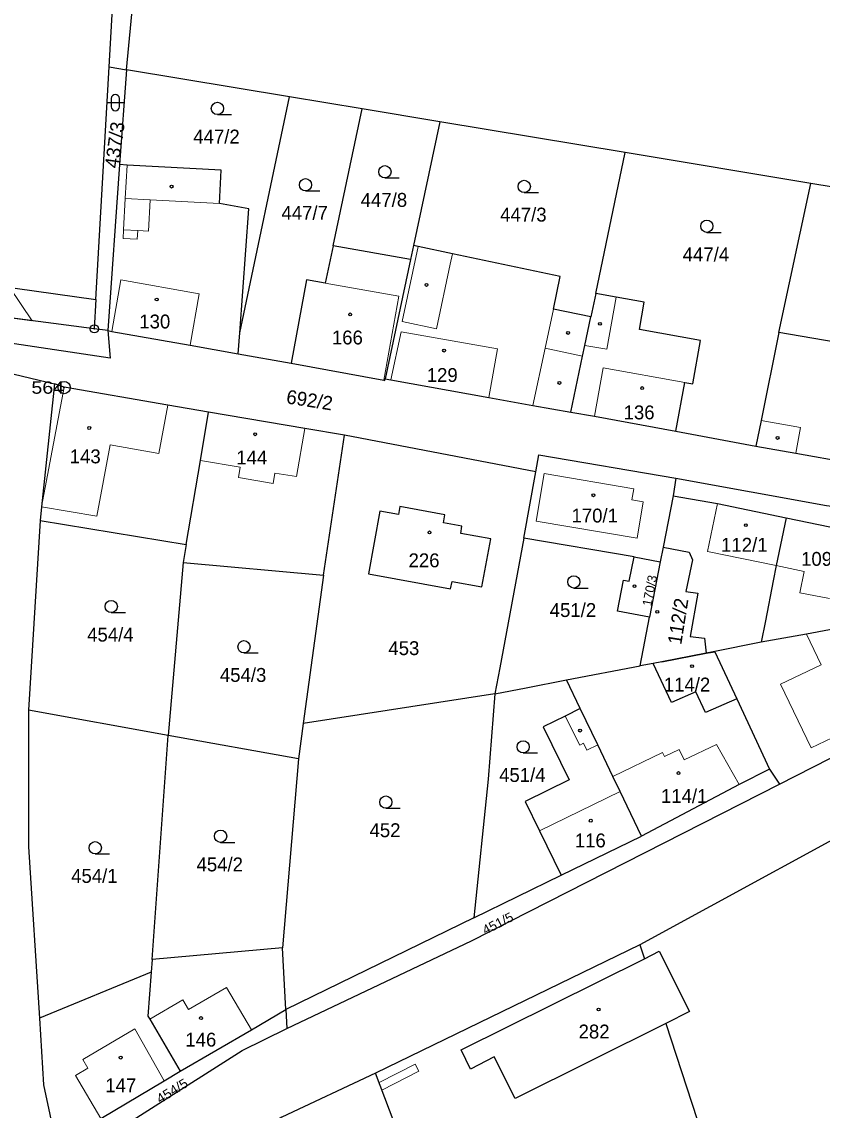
# Model space of a CAD drawing. Extents: x -758887 to -754328, y -1031688 to -1029144.
# Drawn here: x -756696 to -756598, y -1030326.2 to -1030192.8 of the extents above; entities that cross this region are included whole.
import ezdxf
from ezdxf.enums import TextEntityAlignment as Align

# ---------------------------------------------------------------- set-up
doc = ezdxf.new("R2010")
doc.units = 0
doc.header["$LTSCALE"] = 0.68
for name, color, linetype, lineweight in [('1', 7, 'Continuous', 25), ('13', 7, 'Continuous', 13), ('3', 7, 'Continuous', 25), ('4', 7, 'Continuous', 13), ('5', 7, 'Continuous', 25), ('8', 7, 'Continuous', 25)]:
    doc.layers.add(name, color=color, linetype=linetype, lineweight=lineweight)
doc.layers.add('2', color=7, linetype='Continuous')

msp = doc.modelspace()

# ---------------------------------------------------------------- linework, layer by layer
at = {"layer": '1'}
for p, q in [((-756685.29, -1030198.37), (-756683.17, -1030198.72)), ((-756683.17, -1030198.72), (-756684.01, -1030210.35)), ((-756654.32, -1030203.52), (-756663.2, -1030202.04)), ((-756657.85, -1030220.28), (-756654.32, -1030203.52)), ((-756644.8, -1030205.1), (-756654.32, -1030203.52)), ((-756625.69, -1030226.14), (-756622.11, -1030208.87)), ((-756684.01, -1030210.35), (-756685.47, -1030230.69)), ((-756648.38, -1030221.99), (-756657.85, -1030220.28)), ((-756687.12, -1030230.47), (-756737.93, -1030223.79)), ((-756625.69, -1030226.14), (-756626.3, -1030229.01)), ((-756686.91, -1030226.87), (-756687.12, -1030230.47)), ((-756685.47, -1030230.69), (-756687.12, -1030230.47)), ((-756584.9, -1030234.13), (-756603.26, -1030230.9)), ((-756669.48, -1030233.55), (-756663.02, -1030234.67)), ((-756700.62, -1030235.14), (-756691.98, -1030237.21)), ((-756633.02, -1030248.01), (-756656.47, -1030243.49)), ((-756615.89, -1030242.99), (-756606.1, -1030244.83)), ((-756634.51, -1030256.1), (-756633.02, -1030248.01)), ((-756615.89, -1030248.78), (-756616.22, -1030250.92)), ((-756693.76, -1030253.97), (-756695.18, -1030277.2)), ((-756620.97, -1030258.39), (-756634.51, -1030256.1)), ((-756676.24, -1030259.12), (-756678.07, -1030280.29)), ((-756620.97, -1030258.39), (-756617.79, -1030259.04)), ((-756659.04, -1030260.65), (-756661.53, -1030278.84)), ((-756599.88, -1030267.89), (-756605.42, -1030268.88)), ((-756612.17, -1030270.21), (-756617.59, -1030271.27)), ((-756618.67, -1030271.47), (-756620.26, -1030271.77)), ((-756617.59, -1030271.27), (-756618.67, -1030271.47)), ((-756638.04, -1030275.18), (-756661.53, -1030278.84)), ((-756603.2, -1030286.25), (-756581.92, -1030275.41)), ((-756608.43, -1030275.79), (-756612.24, -1030277.5)), ((-756662.12, -1030283.18), (-756678.07, -1030280.29)), ((-756640.63, -1030302.65), (-756663.67, -1030313.89)), ((-756620.28, -1030305.94), (-756652.67, -1030321.7)), ((-756620.28, -1030305.94), (-756619.72, -1030307.65)), ((-756642.2, -1030318.84), (-756619.72, -1030307.65)), ((-756680.15, -1030309.29), (-756693.84, -1030314.92)), ((-756663.67, -1030313.89), (-756663.55, -1030316.2)), ((-756614.22, -1030314.14), (-756617.12, -1030315.59)), ((-756617.12, -1030315.59), (-756635.56, -1030324.79)), ((-756647.29, -1030335.79), (-756652.67, -1030321.7))]:
    msp.add_line(p, q, dxfattribs=at)
for points in [[(-756685.29, -1030198.37), (-756679.09, -1030089.54), (-756699.14, -1030088.53)], [(-756683.17, -1030198.72), (-756678.44, -1030149.27), (-756677.83, -1030132.01)], [(-756696.82, -1030225.47), (-756686.91, -1030226.87), (-756685.29, -1030198.37)], [(-756669.29, -1030230.97), (-756663.2, -1030202.04), (-756683.17, -1030198.72)], [(-756622.11, -1030208.87), (-756644.8, -1030205.1), (-756648.01, -1030220.26)], [(-756603.26, -1030230.9), (-756599.37, -1030212.64), (-756622.11, -1030208.87)], [(-756669.29, -1030230.97), (-756668.18, -1030215.77), (-756671.79, -1030215.12), (-756671.57, -1030211.03), (-756683.1, -1030210.4), (-756684.01, -1030210.35)], [(-756584.9, -1030234.13), (-756582.7, -1030215.41), (-756599.37, -1030212.64)], [(-756657.85, -1030220.28), (-756658.82, -1030224.88), (-756661.12, -1030224.47), (-756663.02, -1030234.67)], [(-756648.01, -1030220.26), (-756648.38, -1030221.99), (-756651.47, -1030236.61)], [(-756626.3, -1030229.01), (-756630.89, -1030228.04), (-756630.05, -1030224.07), (-756643.24, -1030221.28), (-756647.45, -1030220.38), (-756648.01, -1030220.26)], [(-756685.47, -1030230.69), (-756685.18, -1030234.07), (-756755.52, -1030223.53)], [(-756615.89, -1030242.99), (-756614.8, -1030237.03), (-756613.81, -1030237.2), (-756612.86, -1030231.89), (-756620.34, -1030230.55), (-756619.75, -1030227.2), (-756623.19, -1030226.59), (-756625.69, -1030226.14)], [(-756628.76, -1030240.67), (-756627.31, -1030233.81), (-756627.03, -1030232.5), (-756626.3, -1030229.01)], [(-756685.47, -1030230.69), (-756684.98, -1030230.78), (-756675.38, -1030232.47), (-756669.48, -1030233.55), (-756669.29, -1030230.97)], [(-756603.26, -1030230.9), (-756605.44, -1030241.7), (-756606.1, -1030244.83)], [(-756663.02, -1030234.67), (-756651.66, -1030236.75), (-756651.51, -1030236.78), (-756651.47, -1030236.61)], [(-756651.47, -1030236.61), (-756650.78, -1030236.73), (-756638.78, -1030238.89), (-756633.39, -1030239.88), (-756628.76, -1030240.67)], [(-756691.98, -1030237.21), (-756693.58, -1030252.28), (-756693.76, -1030253.97), (-756675.86, -1030256.9)], [(-756673.13, -1030240.68), (-756678.1, -1030239.84), (-756690.8, -1030237.63), (-756691.98, -1030237.21)], [(-756675.86, -1030256.9), (-756674.12, -1030246.6), (-756673.13, -1030240.68)], [(-756656.47, -1030243.49), (-756661.34, -1030242.67), (-756673.13, -1030240.68)], [(-756628.76, -1030240.67), (-756625.86, -1030241.19), (-756615.89, -1030242.99)], [(-756675.86, -1030256.9), (-756676.24, -1030259.12), (-756659.04, -1030260.65), (-756656.47, -1030243.49)], [(-756606.1, -1030244.83), (-756601.18, -1030245.71), (-756594.78, -1030246.84), (-756587.36, -1030248.23)], [(-756633.02, -1030248.01), (-756632.67, -1030245.9), (-756615.89, -1030248.78)], [(-756615.89, -1030248.78), (-756597.44, -1030252.13), (-756568.84, -1030255.8), (-756549.84, -1030258.9)], [(-756616.22, -1030250.92), (-756617.44, -1030257.21), (-756617.79, -1030259.04), (-756619.11, -1030265.82)], [(-756616.22, -1030250.92), (-756610.79, -1030251.87), (-756602.37, -1030253.61)], [(-756602.37, -1030253.61), (-756603.58, -1030259.49), (-756603.95, -1030261.35), (-756604.9, -1030266.26), (-756605.42, -1030268.88)], [(-756602.37, -1030253.61), (-756591.67, -1030255.82), (-756585.38, -1030257.07)], [(-756634.51, -1030256.1), (-756637.46, -1030272.02), (-756638.04, -1030275.18)], [(-756617.44, -1030257.21), (-756614.25, -1030257.83), (-756613.83, -1030258.76), (-756614.66, -1030262.66), (-756613.2, -1030262.85), (-756614.13, -1030268.18), (-756612.37, -1030268.37), (-756612.17, -1030270.21)], [(-756619.11, -1030265.82), (-756623.05, -1030265.05), (-756622.3, -1030261.25), (-756621.59, -1030261.4), (-756620.97, -1030258.39)], [(-756638.04, -1030275.18), (-756634.23, -1030274.45), (-756629.27, -1030273.5), (-756620.26, -1030271.77), (-756619.11, -1030265.82)], [(-756589.67, -1030265.94), (-756593.6, -1030266.69), (-756599.88, -1030267.89)], [(-756605.42, -1030268.88), (-756611.31, -1030270.04), (-756612.17, -1030270.21)], [(-756617.59, -1030271.27), (-756612.17, -1030270.23), (-756611.11, -1030270.03), (-756608.43, -1030275.79)], [(-756612.24, -1030277.5), (-756613.45, -1030274.95), (-756616.42, -1030276.26), (-756618.67, -1030271.47)], [(-756620.08, -1030292.62), (-756622.71, -1030287.16), (-756623.59, -1030285.32), (-756625.45, -1030281.44), (-756627.59, -1030276.99), (-756629.27, -1030273.5)], [(-756638.04, -1030275.18), (-756638.89, -1030285.64), (-756640.63, -1030302.65), (-756629.92, -1030297.42)], [(-756608.43, -1030275.79), (-756604.42, -1030284.43), (-756603.2, -1030286.25)], [(-756680.04, -1030307.74), (-756678.07, -1030280.29), (-756695.18, -1030277.2)], [(-756695.18, -1030277.2), (-756695.17, -1030293.95), (-756693.84, -1030314.92)], [(-756627.59, -1030276.99), (-756629.45, -1030277.92), (-756632.13, -1030279.26), (-756628.95, -1030285.73), (-756634.33, -1030288.38), (-756632.58, -1030291.98), (-756629.92, -1030297.42), (-756620.08, -1030292.62)], [(-756661.53, -1030278.84), (-756662.12, -1030283.18), (-756664.05, -1030306.34)], [(-756604.42, -1030284.43), (-756608.13, -1030286.3), (-756620.08, -1030292.62)], [(-756663.55, -1030316.2), (-756640.92, -1030305.48), (-756603.2, -1030286.25)], [(-756559.33, -1030353.52), (-756560.95, -1030349.83), (-756566.54, -1030335.72), (-756566.01, -1030335.51), (-756570.59, -1030325.43), (-756584.98, -1030290.58), (-756586.29, -1030287.41), (-756620.28, -1030305.94)], [(-756663.67, -1030313.89), (-756664.05, -1030306.34), (-756680.04, -1030307.74), (-756680.15, -1030309.29)], [(-756619.72, -1030307.65), (-756617.92, -1030306.75), (-756614.22, -1030314.14)], [(-756680.15, -1030309.29), (-756680.54, -1030314.7), (-756680.33, -1030315.05), (-756676.61, -1030321.45)], [(-756676.61, -1030321.45), (-756667.88, -1030316.35), (-756663.67, -1030313.89)], [(-756693.84, -1030314.92), (-756693.32, -1030323.11), (-756691.79, -1030330.38)], [(-756617.12, -1030315.59), (-756606.24, -1030348.88), (-756599.08, -1030379.53)], [(-756691.23, -1030333.05), (-756669, -1030318.91), (-756663.55, -1030316.2)], [(-756635.56, -1030324.79), (-756638.13, -1030319.69), (-756641.05, -1030321.19), (-756642.2, -1030318.84)], [(-756691.79, -1030330.38), (-756686.33, -1030327.22), (-756678.54, -1030322.6), (-756676.61, -1030321.45)], [(-756652.67, -1030321.7), (-756664.14, -1030327.08), (-756667.44, -1030329.04), (-756666.51, -1030330.91)]]:
    msp.add_lwpolyline(points, dxfattribs=at)
msp.add_lwpolyline([(-756649.87, -1030253.23), (-756652.14, -1030252.82), (-756653.53, -1030260.49), (-756643.48, -1030262.33), (-756643.29, -1030261.42), (-756639.63, -1030262.1), (-756638.56, -1030256.2), (-756642.22, -1030255.53), (-756642.09, -1030254.66), (-756644.34, -1030254.26), (-756644.17, -1030253.26), (-756649.69, -1030252.24)], close=True, dxfattribs=at)
at = {"layer": '13'}
for points in [[(-756694.74, -1030229.47), (-756697.51, -1030225.37), (-756704.92, -1030224.33), (-756702.5, -1030228.45)], [(-756652.24, -1030322.82), (-756651.88, -1030323.76), (-756647.36, -1030321.45), (-756647.81, -1030320.56)]]:
    msp.add_lwpolyline(points, close=True, dxfattribs=at)
at = {"layer": '3'}
for p, q in [((-756685.051, -1030202.251), (-756685.051, -1030203.252)), ((-756684.049, -1030203.252), (-756684.049, -1030202.251)), ((-756685.551, -1030202.751), (-756683.549, -1030202.751)), ((-756672.043, -1030204.21), (-756670.293, -1030204.21)), ((-756651.523, -1030211.97), (-756649.773, -1030211.97)), ((-756661.243, -1030213.56), (-756659.493, -1030213.56)), ((-756634.453, -1030213.77), (-756632.703, -1030213.77)), ((-756612.093, -1030218.65), (-756610.343, -1030218.65)), ((-756628.383, -1030262.23), (-756626.633, -1030262.23)), ((-756685.043, -1030265.24), (-756683.293, -1030265.24)), ((-756668.783, -1030270.18), (-756667.033, -1030270.18)), ((-756634.583, -1030282.44), (-756632.833, -1030282.44)), ((-756651.403, -1030289.21), (-756649.653, -1030289.21)), ((-756671.643, -1030293.4), (-756669.893, -1030293.4)), ((-756687.003, -1030294.81), (-756685.253, -1030294.81))]:
    msp.add_line(p, q, dxfattribs=at)
for centre in [(-756672.0429, -1030203.4598), (-756651.5229, -1030211.2198), (-756661.2429, -1030212.8098), (-756634.4529, -1030213.0198), (-756612.0929, -1030217.8998), (-756628.3829, -1030261.4798), (-756685.0429, -1030264.4898), (-756668.7829, -1030269.4298), (-756634.5829, -1030281.6898), (-756651.4029, -1030288.4598), (-756671.6429, -1030292.6498), (-756687.0029, -1030294.0598)]:
    msp.add_circle(centre, 0.75, dxfattribs=at)
for centre, start, end in [((-756684.55, -1030202.2509), 0, 180), ((-756684.55, -1030203.2509), 180, 359.98789)]:
    msp.add_arc(centre, 0.5, start, end, dxfattribs=at)
at = {"layer": '4'}
for p, q in [((-756683.33, -1030214.49), (-756683.1, -1030210.4)), ((-756680.28, -1030214.66), (-756683.33, -1030214.49)), ((-756680.28, -1030214.66), (-756680.49, -1030218.5)), ((-756671.79, -1030215.12), (-756680.28, -1030214.66)), ((-756681.85, -1030219.48), (-756683.59, -1030219.38)), ((-756681.79, -1030218.43), (-756683.53, -1030218.34)), ((-756681.79, -1030218.43), (-756681.85, -1030219.48)), ((-756680.49, -1030218.5), (-756681.79, -1030218.43)), ((-756647.45, -1030220.38), (-756649.4, -1030229.58)), ((-756643.51, -1030222.55), (-756643.24, -1030221.28)), ((-756643.51, -1030222.55), (-756645.19, -1030230.47)), ((-756683.87, -1030224.48), (-756684.98, -1030230.78)), ((-756683.87, -1030224.48), (-756674.27, -1030226.17)), ((-756658.82, -1030224.88), (-756649.8, -1030226.47)), ((-756674.27, -1030226.17), (-756675.38, -1030232.47)), ((-756651.66, -1030236.75), (-756649.8, -1030226.47)), ((-756624.34, -1030232.98), (-756623.19, -1030226.59)), ((-756630.89, -1030228.04), (-756631.9, -1030232.84)), ((-756645.19, -1030230.47), (-756649.4, -1030229.58)), ((-756649.53, -1030230.83), (-756650.78, -1030236.73)), ((-756637.71, -1030232.93), (-756649.53, -1030230.83)), ((-756637.71, -1030232.93), (-756638.78, -1030238.89)), ((-756633.39, -1030239.88), (-756631.9, -1030232.84)), ((-756627.31, -1030233.81), (-756631.9, -1030232.84)), ((-756627.03, -1030232.5), (-756624.34, -1030232.98)), ((-756624.79, -1030235.24), (-756625.86, -1030241.19)), ((-756624.79, -1030235.24), (-756614.8, -1030237.03)), ((-756693.58, -1030252.28), (-756690.8, -1030237.63)), ((-756605.44, -1030241.7), (-756600.62, -1030242.56)), ((-756600.62, -1030242.56), (-756601.18, -1030245.71)), ((-756633.01, -1030254.02), (-756632.03, -1030248.2)), ((-756632.03, -1030248.2), (-756621.03, -1030250.06)), ((-756621.26, -1030251.44), (-756621.03, -1030250.06)), ((-756620.63, -1030256.11), (-756633.01, -1030254.02)), ((-756603.58, -1030259.49), (-756600.15, -1030260.2)), ((-756600.15, -1030260.2), (-756600.71, -1030262.81)), ((-756600.71, -1030262.81), (-756597.05, -1030263.52)), ((-756599.88, -1030267.89), (-756598.1, -1030271.64)), ((-756598.1, -1030271.64), (-756603.08, -1030274)), ((-756603.08, -1030274), (-756599.29, -1030281.83)), ((-756599.29, -1030281.83), (-756585.5, -1030275.09)), ((-756629.45, -1030277.92), (-756627.66, -1030281.5)), ((-756627.18, -1030281.26), (-756627.66, -1030281.5)), ((-756627.18, -1030281.26), (-756626.78, -1030282.08)), ((-756626.78, -1030282.08), (-756625.45, -1030281.44)), ((-756615.46, -1030282.03), (-756617.27, -1030282.89)), ((-756614.86, -1030283.29), (-756615.46, -1030282.03)), ((-756610.89, -1030281.39), (-756614.86, -1030283.29)), ((-756610.89, -1030281.39), (-756608.13, -1030286.3)), ((-756617.5, -1030282.4), (-756623.59, -1030285.32)), ((-756617.27, -1030282.89), (-756617.5, -1030282.4)), ((-756622.71, -1030287.16), (-756632.58, -1030291.98)), ((-756680.33, -1030315.05), (-756676.28, -1030312.68)), ((-756676.28, -1030312.68), (-756675.57, -1030313.89)), ((-756682.14, -1030316.25), (-756688.51, -1030320.02)), ((-756678.54, -1030322.6), (-756682.14, -1030316.25)), ((-756688.51, -1030320.02), (-756687.89, -1030321.05)), ((-756687.89, -1030321.05), (-756689.44, -1030321.97)), ((-756689.44, -1030321.97), (-756686.33, -1030327.22))]:
    msp.add_line(p, q, dxfattribs=at)
for points in [[(-756683.59, -1030219.38), (-756683.53, -1030218.34), (-756683.33, -1030214.49)], [(-756693.58, -1030252.28), (-756686.82, -1030253.44), (-756685.16, -1030244.7), (-756679.22, -1030245.74), (-756678.1, -1030239.84)], [(-756674.12, -1030246.6), (-756669.24, -1030247.42), (-756669.46, -1030248.7), (-756665.22, -1030249.42), (-756665, -1030248.14), (-756662.34, -1030248.58), (-756661.34, -1030242.67)], [(-756620.63, -1030256.11), (-756619.88, -1030251.67), (-756621.26, -1030251.44)], [(-756603.58, -1030259.49), (-756612, -1030257.75), (-756610.79, -1030251.87)], [(-756675.57, -1030313.89), (-756670.91, -1030311.17), (-756667.88, -1030316.35)]]:
    msp.add_lwpolyline(points, dxfattribs=at)
at = {"layer": '5'}
for centre in [(-756677.6468, -1030213.0392), (-756646.4268, -1030225.0892), (-756679.4768, -1030226.8692), (-756655.7768, -1030228.6992), (-756625.1768, -1030229.8592), (-756629.0868, -1030230.9692), (-756644.2768, -1030233.1392), (-756630.1468, -1030237.0992), (-756620.0168, -1030237.7292), (-756687.7368, -1030242.6192), (-756667.4068, -1030243.3892), (-756603.4168, -1030243.8392), (-756625.9868, -1030250.8692), (-756646.0568, -1030255.4092), (-756607.3168, -1030254.5192), (-756620.9468, -1030262.0092), (-756618.1568, -1030265.1392), (-756613.8968, -1030271.7992), (-756627.6168, -1030279.6992), (-756615.5568, -1030284.8992), (-756626.3168, -1030290.7392), (-756625.3468, -1030313.8792), (-756674.0468, -1030314.9292), (-756683.8868, -1030319.7692)]:
    msp.add_circle(centre, 0.175, dxfattribs=at)
at = {"layer": '8'}
for centre, radius in [((-756687.12, -1030230.4699), 0.5), ((-756687.12, -1030230.4699), 0.0303), ((-756690.81, -1030237.6698), 0.75), ((-756690.81, -1030237.6698), 0.03)]:
    msp.add_circle(centre, radius, dxfattribs=at)

# ---------------------------------------------------------------- texts
at = {"layer": '2'}
for s, height, rotation, p in [('437/3', 1.7, 82, (-756683.7769, -1030208.0488)), ('692/2', 1.7, 351, (-756660.8745, -1030240.0328)), ('170/3', 1.139, 79, (-756618.5263, -1030262.6552)), ('112/2', 1.7, 81, (-756614.7762, -1030266.4345))]:
    msp.add_text(s, height=height, rotation=rotation, dxfattribs=at).set_placement(p, align=Align.CENTER)
for s, p in [('447/2', (-756672.15, -1030207.76)), ('447/8', (-756651.64, -1030215.52)), ('447/7', (-756661.35, -1030217.11)), ('447/3', (-756634.56, -1030217.32)), ('447/4', (-756612.2, -1030222.2)), ('130', (-756679.709, -1030230.42)), ('166', (-756656.119, -1030232.38)), ('129', (-756644.499, -1030236.98)), ('136', (-756620.389, -1030241.56)), ('143', (-756688.229, -1030246.95)), ('144', (-756667.829, -1030247.09)), ('170/1', (-756625.82, -1030254.2)), ('112/1', (-756607.5, -1030257.78)), ('226', (-756646.729, -1030259.69)), ('109/1', (-756597.7, -1030259.51)), ('451/2', (-756628.49, -1030265.78)), ('454/4', (-756685.15, -1030268.79)), ('453', (-756649.199, -1030270.45)), ('454/3', (-756668.89, -1030273.73)), ('451/4', (-756634.69, -1030285.99)), ('452', (-756651.509, -1030292.76)), ('116', (-756626.369, -1030294.01)), ('454/2', (-756671.75, -1030296.95)), ('454/1', (-756687.11, -1030298.36)), ('146', (-756674.069, -1030318.42)), ('282', (-756625.899, -1030317.43)), ('147', (-756683.879, -1030324.02))]:
    msp.add_text(s, height=1.7, dxfattribs=at).set_placement(p, align=Align.CENTER)
for s, p in [('114/2', (-756617.36, -1030274.91)), ('114/1', (-756617.71, -1030288.57))]:
    msp.add_text(s, height=1.7, dxfattribs=at).set_placement(p)
for s, rotation, width, p in [('451/5', 27, 1.05, (-756637.4383, -1030303.8297)), ('454/5', 32, 1.1, (-756677.2866, -1030324.3267))]:
    msp.add_text(s, height=1.14, rotation=rotation, dxfattribs=dict(at, width=width)).set_placement(p, align=Align.CENTER)
at = {"layer": '8', "width": 1.2}
msp.add_text('564', height=1.5, dxfattribs=at).set_placement((-756690.81, -1030238.42), align=Align.RIGHT)

doc.saveas('drawing.dxf')
